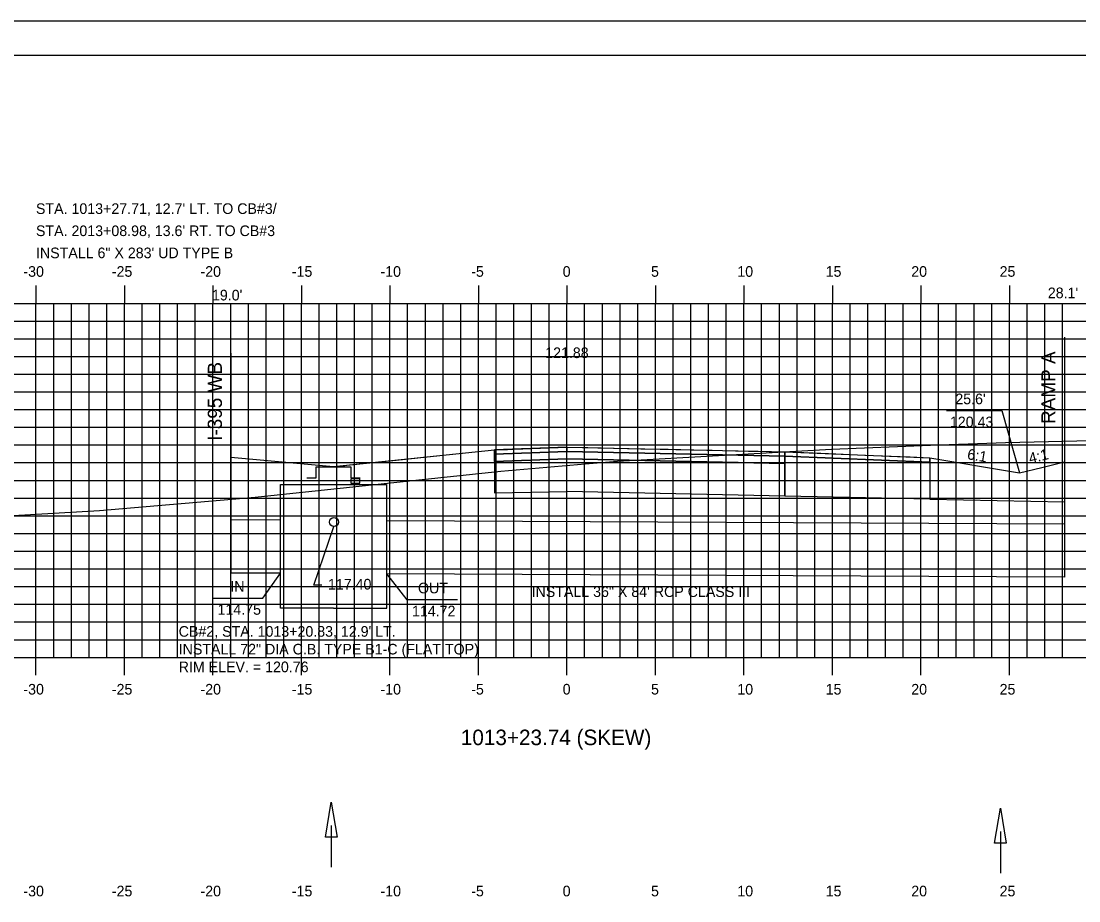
# Model space of a CAD drawing. Extents: x 852625 to 852797, y 365624 to 365734.
# Drawn here: x 852677.7 to 852737.5, y 365684.3 to 365734 of the extents above; entities that cross this region are included whole.
import ezdxf

# ---------------------------------------------------------------- set-up
doc = ezdxf.new("R2010")
doc.units = 0
for name, color, linetype in [('ANNOTATION', 7, 'Continuous'), ('BORDER', 7, 'Continuous'), ('D_Drainage_CB_TypeA1-B1', 7, 'Continuous'), ('D_Drainage_Culvert', 7, 'Continuous'), ('D_Drainage_Ditch_Line', 7, 'Continuous'), ('D_Drainage_Text', 7, 'Continuous'), ('D_Roadway_Centerline', 7, 'Continuous'), ('D_Roadway_Centerline_Text', 7, 'Continuous'), ('D_Roadway_Edge_Shoulder', 7, 'Continuous'), ('D_Roadway_Edge_TW', 7, 'Continuous'), ('D_Roadway_FinishedGrade', 7, 'Continuous'), ('D_Roadway_Pavement', 7, 'Continuous'), ('D_Roadway_SubGrade', 7, 'Continuous'), ('D_Text_Standard', 7, 'Continuous'), ('Default', 7, 'Continuous'), ('H_V ANNOTATION', 7, 'Continuous'), ('MAJOR', 7, 'Continuous'), ('MINOR', 7, 'Continuous'), ('PLOT BOUNDARY', 7, 'Continuous'), ('S_Roadway_Centerline', 7, 'Continuous')]:
    doc.layers.add(name, color=color, linetype=linetype)

msp = doc.modelspace()

# ---------------------------------------------------------------- linework, layer by layer
at = {"layer": 'ANNOTATION'}
for points in [[(852730.001, 365711.964), (852733.111, 365711.964), (852734.122, 365708.459)], [(852694.706, 365702.105), (852694.245, 365702.105), (852695.382, 365705.422)], [(852688.515, 365701.371), (852691.361, 365701.371), (852692.357, 365702.777)], [(852702.358, 365701.282), (852699.512, 365701.282), (852698.363, 365702.747)]]:
    msp.add_lwpolyline(points, dxfattribs=at)
at = {"layer": 'BORDER'}
msp.add_lwpolyline([(852633.549, 365627.027), (852793.549, 365627.027), (852793.549, 365732.027), (852633.549, 365732.027)], close=True, dxfattribs=at)
at = {"layer": 'D_Drainage_CB_TypeA1-B1'}
msp.add_line((852692.363, 365707.798), (852698.357, 365707.798), dxfattribs=at)
for points in [[(852693.848, 365708.175), (852694.373, 365708.175), (852694.373, 365708.798), (852696.342, 365708.798), (852696.342, 365708.175), (852696.867, 365708.175)], [(852695.357, 365700.798), (852692.363, 365700.798), (852692.363, 365707.798)], [(852695.357, 365700.798), (852698.363, 365700.798), (852698.363, 365707.798)]]:
    msp.add_lwpolyline(points, dxfattribs=at)
msp.add_lwpolyline([(852696.342, 365708.111), (852696.342, 365707.861), (852696.842, 365707.861), (852696.842, 365708.111)], close=True, dxfattribs=at)
at = {"layer": 'D_Drainage_Culvert'}
for p, q in [((852692.363, 365705.777), (852689.559, 365705.791)), ((852711.834, 365704.025), (852717.745, 365704.025)), ((852692.357, 365702.777), (852689.559, 365702.791))]:
    msp.add_line(p, q, dxfattribs=at)
for points in [[(852736.651, 365705.556), (852698.363, 365705.747)], [(852736.636, 365702.556), (852698.363, 365702.747)]]:
    msp.add_lwpolyline(points, dxfattribs=at)
msp.add_circle((852695.382, 365705.672), 0.25, dxfattribs=at)
at = {"layer": 'D_Drainage_Ditch_Line'}
for p, q in [((852695.228, 365688.526), (852695.228, 365686.177)), ((852733.037, 365688.192), (852733.037, 365685.843))]:
    msp.add_line(p, q, dxfattribs=at)
for points in [[(852695.556, 365687.87), (852694.9, 365687.87), (852695.228, 365689.839)], [(852733.365, 365687.536), (852732.709, 365687.536), (852733.037, 365689.505)]]:
    msp.add_lwpolyline(points, close=True, dxfattribs=at)
at = {"layer": 'D_Roadway_Centerline'}
for p, q in [((852729.052, 365709.304), (852734.122, 365708.459)), ((852729.052, 365706.964), (852736.657, 365706.807))]:
    msp.add_line(p, q, dxfattribs=at)
for points in [[(852695.358, 365708.803), (852695.994, 365708.869), (852696.115, 365708.882), (852698.896, 365709.172), (852700.654, 365709.355), (852701.921, 365709.487), (852704.447, 365709.751), (852705.188, 365709.779), (852705.478, 365709.789), (852705.575, 365709.793), (852708.549, 365709.903), (852709.428, 365709.884), (852709.725, 365709.878), (852712.723, 365709.813), (852714.263, 365709.78), (852715.714, 365709.75), (852716.754, 365709.728), (852717.338, 365709.715), (852718.797, 365709.684), (852719.35, 365709.672), (852720.851, 365709.64), (852722.45, 365709.574), (852723.335, 365709.538), (852725.372, 365709.454), (852727.873, 365709.352), (852727.93, 365709.35), (852727.939, 365709.349), (852729.053, 365709.304)], [(852695.358, 365708.803), (852704.447, 365709.751)], [(852695.358, 365708.803), (852704.447, 365709.751)], [(852689.559, 365709.346), (852695.358, 365708.802)], [(852734.122, 365708.459), (852735.375, 365708.761), (852736.657, 365709.07)]]:
    msp.add_lwpolyline(points, dxfattribs=at)
at = {"layer": 'D_Roadway_Edge_Shoulder'}
for points in [[(852708.548, 365709.903), (852704.447, 365709.751), (852704.447, 365709.501), (852708.548, 365709.653)], [(852720.851, 365709.64), (852729.052, 365709.304), (852729.052, 365709.054), (852720.851, 365709.39)]]:
    msp.add_lwpolyline(points, close=True, dxfattribs=at)
at = {"layer": 'D_Roadway_Edge_TW'}
msp.add_lwpolyline([(852708.548, 365709.903), (852720.851, 365709.64), (852720.851, 365709.39), (852708.548, 365709.653)], close=True, dxfattribs=at)
msp.add_lwpolyline([(852720.851, 365709.64), (852720.851, 365709.473)], dxfattribs=at)
at = {"layer": 'D_Roadway_FinishedGrade'}
for p, q in [((852704.447, 365709.751), (852704.447, 365709.501)), ((852708.548, 365709.903), (852708.548, 365709.653)), ((852720.851, 365709.64), (852720.851, 365709.39)), ((852729.052, 365709.304), (852729.052, 365709.054))]:
    msp.add_line(p, q, dxfattribs=at)
at = {"layer": 'D_Roadway_Pavement'}
for points in [[(852708.548, 365709.653), (852704.447, 365709.501), (852704.447, 365709.084), (852708.548, 365709.236)], [(852708.548, 365709.653), (852720.851, 365709.39), (852720.851, 365708.973), (852708.548, 365709.236)]]:
    msp.add_lwpolyline(points, close=True, dxfattribs=at)
msp.add_lwpolyline([(852720.851, 365709.473), (852720.851, 365708.973)], dxfattribs=at)
msp.add_lwpolyline([(852720.851, 365709.473), (852720.851, 365708.973)], dxfattribs=at)
at = {"layer": 'D_Roadway_SubGrade'}
for p, q in [((852736.657, 365716.113), (852736.657, 365702.556)), ((852689.559, 365715.221), (852689.559, 365702.791))]:
    msp.add_line(p, q, dxfattribs=at)
for points in [[(852708.548, 365709.236), (852704.447, 365709.084), (852704.447, 365709.584), (852704.447, 365709.751), (852704.447, 365707.331), (852708.548, 365707.403)], [(852708.548, 365709.236), (852720.851, 365708.973), (852720.851, 365707.14), (852708.548, 365707.403)], [(852720.851, 365708.973), (852720.851, 365709.39), (852729.052, 365709.054), (852729.052, 365709.304), (852729.052, 365706.964), (852720.851, 365707.14)]]:
    msp.add_lwpolyline(points, close=True, dxfattribs=at)
msp.add_lwpolyline([(852720.851, 365708.973), (852720.851, 365707.14)], dxfattribs=at)
at = {"layer": 'Default'}
for p, q in [((852729.052, 365709.304), (852734.122, 365708.459)), ((852729.052, 365706.967), (852736.657, 365706.807))]:
    msp.add_line(p, q, dxfattribs=at)
at = {"layer": 'MAJOR'}
for p, q in [((852678.548, 365719.029), (852678.548, 365718.027)), ((852683.548, 365719.029), (852683.548, 365718.027)), ((852688.548, 365719.029), (852688.548, 365718.027)), ((852693.548, 365719.029), (852693.548, 365718.027)), ((852698.548, 365719.029), (852698.548, 365718.027)), ((852703.548, 365719.029), (852703.548, 365718.027)), ((852708.548, 365719.029), (852708.548, 365718.027)), ((852713.548, 365719.029), (852713.548, 365718.027)), ((852718.548, 365719.029), (852718.548, 365718.027)), ((852723.548, 365719.029), (852723.548, 365718.027)), ((852728.548, 365719.029), (852728.548, 365718.027)), ((852733.548, 365719.029), (852733.548, 365718.027)), ((852638.548, 365718.027), (852778.548, 365718.027)), ((852638.548, 365718.027), (852778.548, 365718.027)), ((852678.548, 365698.027), (852678.548, 365718.027)), ((852683.548, 365698.027), (852683.548, 365718.027)), ((852688.548, 365698.027), (852688.548, 365718.027)), ((852693.548, 365698.027), (852693.548, 365718.027)), ((852698.548, 365698.027), (852698.548, 365718.027)), ((852703.548, 365698.027), (852703.548, 365718.027)), ((852708.548, 365698.027), (852708.548, 365718.027)), ((852713.548, 365698.027), (852713.548, 365718.027)), ((852718.548, 365698.027), (852718.548, 365718.027)), ((852723.548, 365698.027), (852723.548, 365718.027)), ((852728.548, 365698.027), (852728.548, 365718.027)), ((852733.548, 365698.027), (852733.548, 365718.027)), ((852638.548, 365713.027), (852778.548, 365713.027)), ((852638.548, 365708.027), (852778.548, 365708.027)), ((852638.548, 365703.027), (852778.548, 365703.027)), ((852638.548, 365698.027), (852778.548, 365698.027)), ((852678.548, 365697.025), (852678.548, 365698.027)), ((852683.548, 365697.025), (852683.548, 365698.027)), ((852688.548, 365697.025), (852688.548, 365698.027)), ((852693.548, 365697.025), (852693.548, 365698.027)), ((852698.548, 365697.025), (852698.548, 365698.027)), ((852703.548, 365697.025), (852703.548, 365698.027)), ((852708.548, 365697.025), (852708.548, 365698.027)), ((852713.548, 365697.025), (852713.548, 365698.027)), ((852718.548, 365697.025), (852718.548, 365698.027)), ((852723.548, 365697.025), (852723.548, 365698.027)), ((852728.548, 365697.025), (852728.548, 365698.027)), ((852733.548, 365697.025), (852733.548, 365698.027))]:
    msp.add_line(p, q, dxfattribs=at)
at = {"layer": 'MINOR'}
for p, q in [((852679.548, 365698.027), (852679.548, 365718.027)), ((852680.548, 365698.027), (852680.548, 365718.027)), ((852681.548, 365698.027), (852681.548, 365718.027)), ((852682.548, 365698.027), (852682.548, 365718.027)), ((852684.548, 365698.027), (852684.548, 365718.027)), ((852685.548, 365698.027), (852685.548, 365718.027)), ((852686.548, 365698.027), (852686.548, 365718.027)), ((852687.548, 365698.027), (852687.548, 365718.027)), ((852689.548, 365698.027), (852689.548, 365718.027)), ((852690.548, 365698.027), (852690.548, 365718.027)), ((852691.548, 365698.027), (852691.548, 365718.027)), ((852692.548, 365698.027), (852692.548, 365718.027)), ((852694.548, 365698.027), (852694.548, 365718.027)), ((852695.548, 365698.027), (852695.548, 365718.027)), ((852696.548, 365698.027), (852696.548, 365718.027)), ((852697.548, 365698.027), (852697.548, 365718.027)), ((852699.548, 365698.027), (852699.548, 365718.027)), ((852700.548, 365698.027), (852700.548, 365718.027)), ((852701.548, 365698.027), (852701.548, 365718.027)), ((852702.548, 365698.027), (852702.548, 365718.027)), ((852704.548, 365698.027), (852704.548, 365718.027)), ((852705.548, 365698.027), (852705.548, 365718.027)), ((852706.548, 365698.027), (852706.548, 365718.027)), ((852707.548, 365698.027), (852707.548, 365718.027)), ((852709.548, 365698.027), (852709.548, 365718.027)), ((852710.548, 365698.027), (852710.548, 365718.027)), ((852711.548, 365698.027), (852711.548, 365718.027)), ((852712.548, 365698.027), (852712.548, 365718.027)), ((852714.548, 365698.027), (852714.548, 365718.027)), ((852715.548, 365698.027), (852715.548, 365718.027)), ((852716.548, 365698.027), (852716.548, 365718.027)), ((852717.548, 365698.027), (852717.548, 365718.027)), ((852719.548, 365698.027), (852719.548, 365718.027)), ((852720.548, 365698.027), (852720.548, 365718.027)), ((852721.548, 365698.027), (852721.548, 365718.027)), ((852722.548, 365698.027), (852722.548, 365718.027)), ((852724.548, 365698.027), (852724.548, 365718.027)), ((852725.548, 365698.027), (852725.548, 365718.027)), ((852726.548, 365698.027), (852726.548, 365718.027)), ((852727.548, 365698.027), (852727.548, 365718.027)), ((852729.548, 365698.027), (852729.548, 365718.027)), ((852730.548, 365698.027), (852730.548, 365718.027)), ((852731.548, 365698.027), (852731.548, 365718.027)), ((852732.548, 365698.027), (852732.548, 365718.027)), ((852734.548, 365698.027), (852734.548, 365718.027)), ((852735.548, 365698.027), (852735.548, 365718.027)), ((852736.548, 365698.027), (852736.548, 365718.027)), ((852638.548, 365717.027), (852778.548, 365717.027)), ((852638.548, 365716.027), (852778.548, 365716.027)), ((852638.548, 365715.027), (852778.548, 365715.027)), ((852638.548, 365714.027), (852778.548, 365714.027)), ((852638.548, 365712.027), (852778.548, 365712.027)), ((852638.548, 365711.027), (852778.548, 365711.027)), ((852638.548, 365710.027), (852778.548, 365710.027)), ((852638.548, 365709.027), (852778.548, 365709.027)), ((852638.548, 365707.027), (852778.548, 365707.027)), ((852638.548, 365706.027), (852778.548, 365706.027)), ((852638.548, 365705.027), (852778.548, 365705.027)), ((852638.548, 365704.027), (852778.548, 365704.027)), ((852638.548, 365702.027), (852778.548, 365702.027)), ((852638.548, 365701.027), (852778.548, 365701.027)), ((852638.548, 365700.027), (852778.548, 365700.027)), ((852638.548, 365699.027), (852778.548, 365699.027))]:
    msp.add_line(p, q, dxfattribs=at)
at = {"layer": 'PLOT BOUNDARY'}
msp.add_lwpolyline([(852625.455, 365623.968), (852795.455, 365623.968), (852795.455, 365733.968), (852625.455, 365733.968)], close=True, dxfattribs=at)
at = {"layer": 'S_Roadway_Centerline'}
msp.add_lwpolyline([(852638.548, 365710.39), (852639.18, 365710.376), (852640.791, 365710.352), (852642.738, 365710.248), (852650.127, 365709.999), (852651.159, 365709.949), (852653.236, 365709.702), (852660.167, 365708.876), (852664.839, 365708.245), (852666.432, 365707.98), (852677.252, 365706.047), (852677.266, 365706.05), (852682.143, 365706.325), (852690.936, 365707.081), (852704.814, 365708.538), (852709.578, 365708.965), (852711.4, 365709.115), (852723.486, 365709.798), (852723.502, 365709.785), (852729.092, 365710.017), (852733.324, 365710.166), (852739.792, 365710.319)], dxfattribs=at)

# ---------------------------------------------------------------- texts
at = {"layer": 'ANNOTATION'}
for s, height, rotation, p in [('RAMP A', 0.8, 90, (852736.15, 365711.212)), ('I-395 WB', 0.8, 90, (852689.052, 365710.258)), ("25.6' ", 0.6, 360, (852730.492, 365712.327)), ('120.43', 0.6, 360, (852730.187, 365711.027)), ('6:1', 0.6, 350.53768, (852731.133, 365709.228)), ('4:1', 0.6, 14.02595, (852734.722, 365708.968))]:
    msp.add_text(s, height=height, rotation=rotation, dxfattribs=at).set_placement(p)
for s, p in [('IN', (852689.529, 365701.734)), ('OUT', (852700.133, 365701.645)), ('114.75', (852688.807, 365700.434)), ('114.72', (852699.793, 365700.345)), ("CB#2, STA. 1013+20.83, 12.9' LT.", (852686.611, 365699.194)), ('INSTALL 72" DIA C.B. TYPE B1-C (FLAT TOP)', (852686.611, 365698.192)), ('RIM ELEV. = 120.76', (852686.611, 365697.19))]:
    msp.add_text(s, height=0.6, dxfattribs=at).set_placement(p)
at = {"layer": 'D_Drainage_Text'}
msp.add_text('INSTALL 36" X 84\' RCP CLASS III', height=0.6, dxfattribs=at).set_placement((852706.549, 365701.439))
at = {"layer": 'D_Roadway_Centerline_Text'}
msp.add_text('121.88', height=0.6, dxfattribs=at).set_placement((852707.32, 365714.935))
at = {"layer": 'D_Text_Standard'}
for s, p in [("STA. 1013+27.71, 12.7' LT. TO CB#3/", (852678.548, 365723.077)), ("STA. 2013+08.98, 13.6' RT. TO CB#3", (852678.548, 365721.827)), ('INSTALL 6" X 283\' UD TYPE B', (852678.548, 365720.577)), ("19.0'", (852688.492, 365718.192)), ("28.1'", (852735.718, 365718.318)), ('117.40', (852695.046, 365701.861))]:
    msp.add_text(s, height=0.6, dxfattribs=at).set_placement(p)
at = {"layer": 'H_V ANNOTATION'}
for s, height, p in [('-30', 0.6, (852677.837, 365719.527)), ('-25', 0.6, (852682.834, 365719.527)), ('-20', 0.6, (852687.842, 365719.527)), ('-15', 0.6, (852693.005, 365719.527)), ('-10', 0.6, (852698.013, 365719.527)), ('-5', 0.6, (852703.139, 365719.527)), ('0', 0.6, (852708.307, 365719.527)), ('5', 0.6, (852713.299, 365719.527)), ('10', 0.6, (852718.174, 365719.527)), ('15', 0.6, (852723.166, 365719.527)), ('20', 0.6, (852728.002, 365719.527)), ('25', 0.6, (852732.994, 365719.527)), ('-30', 0.6, (852677.837, 365695.927)), ('-25', 0.6, (852682.834, 365695.927)), ('-20', 0.6, (852687.842, 365695.927)), ('-15', 0.6, (852693.005, 365695.927)), ('-10', 0.6, (852698.013, 365695.927)), ('-5', 0.6, (852703.139, 365695.927)), ('0', 0.6, (852708.307, 365695.927)), ('5', 0.6, (852713.299, 365695.927)), ('10', 0.6, (852718.174, 365695.927)), ('15', 0.6, (852723.166, 365695.927)), ('20', 0.6, (852728.002, 365695.927)), ('25', 0.6, (852732.994, 365695.927)), ('1013+23.74 (SKEW)', 0.87498, (852702.552, 365693.07)), ('-30', 0.6, (852677.837, 365684.527)), ('-25', 0.6, (852682.834, 365684.527)), ('-20', 0.6, (852687.842, 365684.527)), ('-15', 0.6, (852693.005, 365684.527)), ('-10', 0.6, (852698.013, 365684.527)), ('-5', 0.6, (852703.139, 365684.527)), ('0', 0.6, (852708.307, 365684.527)), ('5', 0.6, (852713.299, 365684.527)), ('10', 0.6, (852718.174, 365684.527)), ('15', 0.6, (852723.166, 365684.527)), ('20', 0.6, (852728.002, 365684.527)), ('25', 0.6, (852732.994, 365684.527))]:
    msp.add_text(s, height=height, dxfattribs=at).set_placement(p)

doc.saveas('drawing.dxf')
